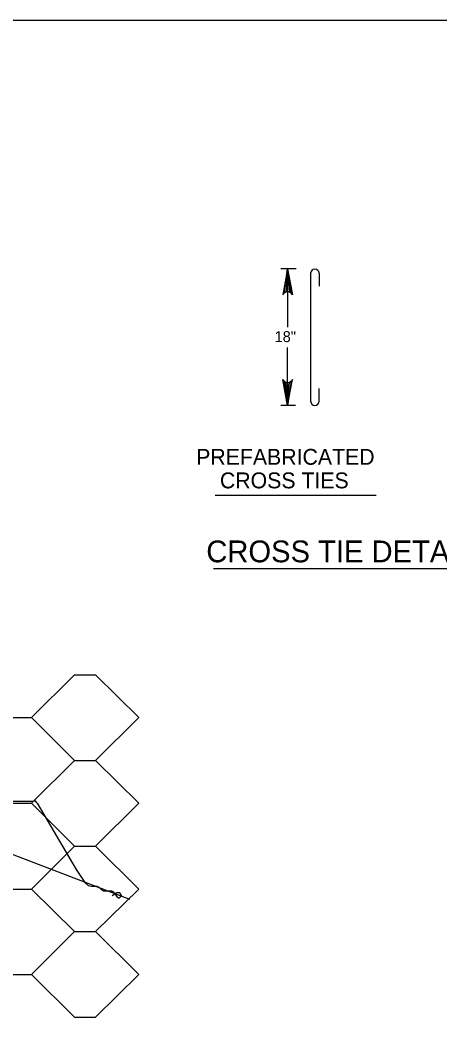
# Model space of a CAD drawing. Extents: x 3 to 3592, y -602 to 1171.
# Drawn here: x 1263.1 to 1378.4, y 280.5 to 561.8 of the extents above; entities that cross this region are included whole.
import ezdxf

# ---------------------------------------------------------------- set-up
doc = ezdxf.new("R2010")
doc.units = 0
for name, color, linetype in [('1', 7, 'Continuous'), ('2', 7, 'Continuous'), ('3', 7, 'Continuous'), ('P', 7, 'Continuous')]:
    doc.layers.add(name, color=color, linetype=linetype)

msp = doc.modelspace()

# ---------------------------------------------------------------- linework, layer by layer
at = {"layer": '1'}
msp.add_lwpolyline([(1668.51, -2.17), (1668.51, 561.83), (882.51, 561.83), (882.51, -2.17), (1668.51, -2.17), (1668.51, 24.19), (1468.51, 24.19), (1468.51, 88.87), (1668.51, 88.87), (1668.51, 117.83), (1468.51, 117.83), (1468.51, -2.17), (1547.31, -2.17), (1547.31, 24.19), (1547.31, -2.17), (1624.31, -2.17), (1624.31, 24.19), (1624.31, 11.88), (1668.51, 11.88)], dxfattribs=at)
for centre, start, end in [((1344.12, 492.19), 2.4896, 177.5104), ((1344.12, 457.04), 182.4896, 357.5104)]:
    msp.add_arc(centre, 1.17, start, end, dxfattribs=at)
at = {"layer": '2'}
for points in [[(1336.61, 493.46), (1337.95, 486.33), (1337.57, 486.88), (1336.61, 493.46), (1337.09, 487.16), (1336.61, 487.24), (1336.61, 493.46), (1336.13, 487.16), (1335.66, 486.88), (1336.61, 493.46), (1335.28, 486.33), (1335.66, 486.88), (1336.13, 487.16), (1336.61, 487.24), (1337.09, 487.16), (1337.57, 486.88)], [(1336.61, 455.87), (1335.28, 463), (1335.66, 462.45), (1336.61, 455.87), (1336.13, 462.17), (1336.61, 462.08), (1336.61, 455.87), (1337.09, 462.17), (1337.57, 462.45), (1336.61, 455.87), (1337.95, 463), (1337.57, 462.45), (1337.09, 462.17), (1336.61, 462.08), (1336.13, 462.17), (1335.66, 462.45)]]:
    msp.add_lwpolyline(points, dxfattribs=at)
at = {"layer": '3'}
for p, q in [((1316.7, 431.12), (1361, 431.12)), ((1316.22, 410.92), (1617.01, 410.92))]:
    msp.add_line(p, q, dxfattribs=at)
at = {"layer": 'P'}
for points in [[(1338.95, 493.46), (1334.78, 493.46)], [(1336.61, 493.46), (1336.61, 477.41)], [(1342.95, 492.24), (1342.95, 456.99)], [(1345.29, 492.24), (1345.29, 488.69)], [(1336.61, 455.87), (1336.61, 471.82)], [(1345.29, 456.99), (1345.29, 460.54)], [(1338.75, 455.87), (1334.78, 455.87)], [(1266.18, 369.92), (1277.97, 381.7)], [(1277.97, 381.7), (1283.76, 381.7)], [(1283.76, 381.7), (1295.65, 369.92)], [(1260.19, 369.92), (1266.18, 369.92)], [(1266.18, 369.92), (1277.97, 358.13)], [(1295.65, 369.92), (1283.76, 358.13)], [(1266.18, 346.34), (1277.97, 358.13)], [(1277.97, 358.13), (1283.76, 358.13)], [(1277.97, 358.13), (1283.76, 358.13)], [(1283.76, 358.13), (1295.65, 346.34)], [(1293.21, 319.83), (1223.92, 346.34)], [(1224.12, 346.95), (1266.69, 346.95)], [(1260.19, 346.34), (1266.18, 346.34)], [(1266.18, 346.34), (1277.97, 334.56)], [(1267.71, 346.34), (1267.61, 346.45), (1267.4, 346.75), (1267, 346.95), (1266.69, 346.95)], [(1267.4, 346.75), (1267.4, 346.85), (1267.3, 346.85), (1267.3, 346.95), (1267.2, 346.95)], [(1267.71, 346.34), (1278.48, 328.06)], [(1295.65, 346.34), (1283.76, 334.56)], [(1266.18, 322.67), (1277.97, 334.56)], [(1277.97, 334.56), (1283.76, 334.56)], [(1277.97, 334.56), (1283.76, 334.56)], [(1283.76, 334.56), (1295.65, 322.67)], [(1278.48, 328.06), (1280.81, 324.5)], [(1280.81, 324.5), (1281.73, 323.69), (1282.64, 323.48), (1284.17, 323.48), (1284.67, 323.28), (1286, 322.27), (1288.23, 322.27), (1288.64, 321.96), (1289.65, 320.64), (1290.06, 320.33), (1290.36, 320.33), (1290.67, 320.54), (1290.87, 320.84), (1290.77, 321.35), (1290.47, 321.66), (1289.65, 321.66), (1288.33, 320.84)], [(1260.19, 322.67), (1266.18, 322.67)], [(1266.18, 322.67), (1277.97, 310.99)], [(1295.65, 322.67), (1283.76, 310.99)], [(1266.18, 299.2), (1277.97, 310.99)], [(1277.97, 310.99), (1283.76, 310.99)], [(1277.97, 310.99), (1283.76, 310.99)], [(1283.76, 310.99), (1295.65, 299.2)], [(1260.19, 299.2), (1266.18, 299.2)], [(1266.18, 299.2), (1277.97, 287.42)], [(1295.65, 299.2), (1283.76, 287.42)], [(1277.97, 287.42), (1283.76, 287.42)]]:
    msp.add_lwpolyline(points, dxfattribs=at)

# ---------------------------------------------------------------- texts
at = {"layer": '3'}
for s, height, p in [('18"', 3, (1333.03, 473.29)), ('PREFABRICATED', 4.375, (1311.46, 439.51)), ('CROSS TIES', 4.375, (1317.99, 433.03)), ('CROSS TIE DETAIL (PREFABRICATED WELDED WIRE GABIONS)', 6, (1314.24, 412.67))]:
    msp.add_text(s, height=height, dxfattribs=at).set_placement(p)

doc.saveas('drawing.dxf')
